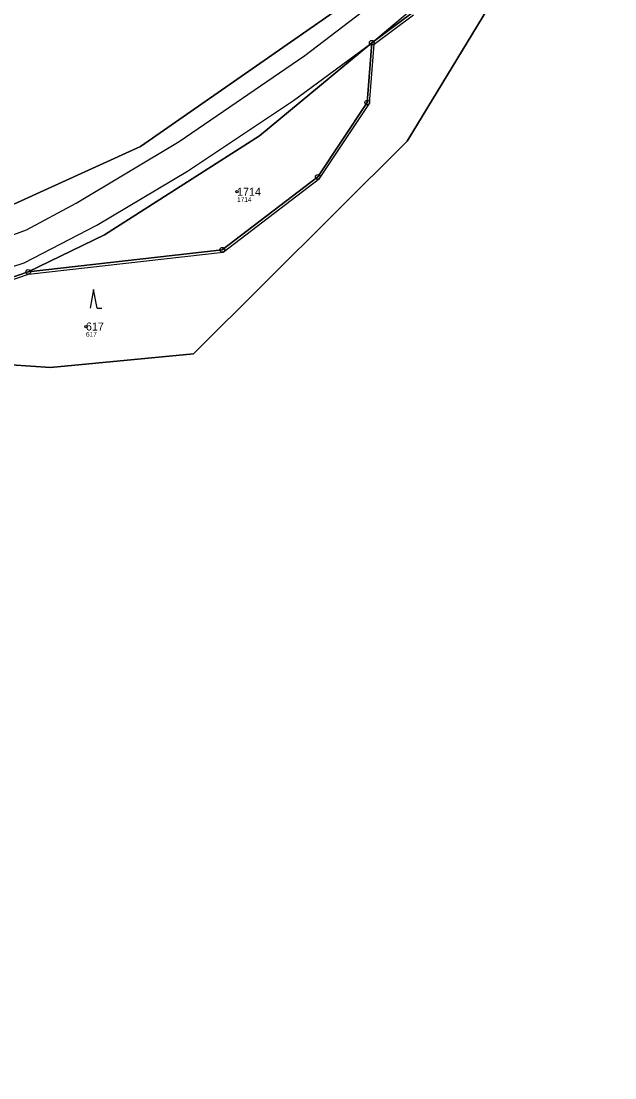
# Model space of a CAD drawing. Extents: x -770088 to -765625, y -1057899 to -1053934.
# Drawn here: x -768186.2 to -768060.2, y -1055836.3 to -1055611.9 of the extents above; entities that cross this region are included whole.
import ezdxf

# ---------------------------------------------------------------- set-up
doc = ezdxf.new("R2010")
doc.units = 0
for name, color, linetype in [('Definiční body', 7, 'Continuous'), ('Hranice parcel', 7, 'Continuous'), ('Parcelní čísla', 7, 'Continuous'), ('Polygon parcely', 7, 'Continuous'), ('Vnitřní kresba', 7, 'Continuous'), ('Značky bodu BP', 7, 'Continuous'), ('Značky kultur', 7, 'Continuous')]:
    doc.layers.add(name, color=color, linetype=linetype)

msp = doc.modelspace()

# ---------------------------------------------------------------- linework, layer by layer
at = {"layer": 'Definiční body'}
for centre in [(-768140.38, -1055648.13), (-768172.45, -1055676.74)]:
    msp.add_circle(centre, 0.25, dxfattribs=at)
at = {"layer": 'Hranice parcel'}
msp.add_line((-768111.79, -1055616.51), (-768103.19, -1055610.16), dxfattribs=at)
for points in [[(-768196.77, -1055684.34), (-768179.99, -1055685.43), (-768149.61, -1055682.54), (-768104.29, -1055637.41), (-768086.16, -1055607.62), (-767983.52, -1055552.84)], [(-768112.56, -1055604.82), (-768160.87, -1055638.55), (-768198.11, -1055655.41), (-768243.55, -1055665.87), (-768292.03, -1055669.76)], [(-768184.7, -1055665.16), (-768143.51, -1055660.46), (-768123.27, -1055644.97), (-768112.75, -1055629.19), (-768111.79, -1055616.51)], [(-768111.79, -1055616.51), (-768135.64, -1055636.25), (-768168.5, -1055657.24), (-768184.7, -1055665.16)], [(-768302.12, -1055683.68), (-768296.49, -1055681.79), (-768292.08, -1055680.32), (-768283.96, -1055679.54), (-768259.94, -1055677.57), (-768237.46, -1055675.58), (-768220.27, -1055672.71), (-768216.46, -1055672.25), (-768209.02, -1055673.46), (-768184.7, -1055665.16)]]:
    msp.add_lwpolyline(points, dxfattribs=at)
at = {"layer": 'Polygon parcely'}
for points in [[(-768112.56, -1055604.82), (-768160.87, -1055638.55), (-768198.11, -1055655.41), (-768243.55, -1055665.87), (-768292.03, -1055669.76), (-768317.01, -1055680.13), (-768323.05, -1055682.64), (-768370.97, -1055702.51), (-768420.02, -1055724.02), (-768455.1, -1055741.72)], [(-768198.11, -1055655.41), (-768160.87, -1055638.55), (-768112.56, -1055604.82)], [(-768086.16, -1055607.62), (-768104.29, -1055637.41), (-768149.61, -1055682.54), (-768179.99, -1055685.43), (-768196.77, -1055684.34), (-768194.75, -1055692.38), (-768224.62, -1055720.54), (-768278.26, -1055739.56), (-768269.37, -1055772.05), (-768226.85, -1055813.83), (-768208.15, -1055859.21), (-768196.97, -1055880.9), (-768222.04, -1055883.64), (-768256.62, -1055887.41), (-768284.6, -1055911.68), (-768295.98, -1055921.55), (-768301.36, -1055926.65), (-768324.43, -1055938.67), (-768353.01, -1055951.04), (-768391.65, -1055965.9), (-768431.86, -1055976.92), (-768474.56, -1055997.15)], [(-768103.19, -1055610.16), (-768111.79, -1055616.51), (-768112.75, -1055629.19), (-768123.27, -1055644.97), (-768143.51, -1055660.46), (-768184.7, -1055665.16), (-768209.02, -1055673.46), (-768216.46, -1055672.25), (-768220.27, -1055672.71), (-768237.46, -1055675.58), (-768259.94, -1055677.57), (-768283.96, -1055679.54), (-768292.08, -1055680.32), (-768296.49, -1055681.79), (-768302.12, -1055683.68), (-768292.5, -1055699.58), (-768286.73, -1055711.22), (-768210.16, -1055683.15), (-768196.77, -1055684.34), (-768179.99, -1055685.43), (-768149.61, -1055682.54), (-768104.29, -1055637.41), (-768086.16, -1055607.62)], [(-768446.8, -1055753.76), (-768414.12, -1055736.49), (-768382.42, -1055722.23), (-768347.5, -1055706.52), (-768302.12, -1055683.68), (-768296.49, -1055681.79), (-768292.08, -1055680.32), (-768283.96, -1055679.54), (-768259.94, -1055677.57), (-768237.46, -1055675.58), (-768220.27, -1055672.71), (-768216.46, -1055672.25), (-768209.02, -1055673.46), (-768184.7, -1055665.16), (-768168.5, -1055657.24), (-768135.64, -1055636.25), (-768111.79, -1055616.51), (-768103.19, -1055610.16)]]:
    msp.add_lwpolyline(points, dxfattribs=at)
msp.add_lwpolyline([(-768135.64, -1055636.25), (-768168.5, -1055657.24), (-768184.7, -1055665.16), (-768143.51, -1055660.46), (-768123.27, -1055644.97), (-768112.75, -1055629.19), (-768111.79, -1055616.51)], close=True, dxfattribs=at)
at = {"layer": 'Vnitřní kresba'}
for p, q in [((-768126.03, -1055619.21), (-768106.98, -1055604.62)), ((-768111.79, -1055616.51), (-768103.81, -1055609.78)), ((-768111.31, -1055616.77), (-768102.92, -1055610.58)), ((-768128.44, -1055628.75), (-768111.79, -1055616.51)), ((-768112.26, -1055629.37), (-768111.31, -1055616.77)), ((-768152.69, -1055637.46), (-768126.03, -1055619.21)), ((-768150.9, -1055643.75), (-768128.44, -1055628.75)), ((-768122.9, -1055645.32), (-768112.26, -1055629.37)), ((-768174.56, -1055650.53), (-768152.69, -1055637.46)), ((-768170.16, -1055655.23), (-768150.9, -1055643.75)), ((-768143.32, -1055660.95), (-768122.9, -1055645.32)), ((-768185.09, -1055656.21), (-768174.56, -1055650.53)), ((-768202.09, -1055662.51), (-768185.09, -1055656.21)), ((-768185.54, -1055663.21), (-768170.16, -1055655.23)), ((-768184.61, -1055665.65), (-768143.32, -1055660.95)), ((-768205.54, -1055669.8), (-768185.54, -1055663.21)), ((-768208.97, -1055673.97), (-768184.61, -1055665.65))]:
    msp.add_line(p, q, dxfattribs=at)
at = {"layer": 'Značky bodu BP'}
for centre, radius in [((-768111.79, -1055616.51), 0.5), ((-768111.79, -1055616.51), 0.0303), ((-768112.75, -1055629.19), 0.5), ((-768112.75, -1055629.19), 0.0303), ((-768123.27, -1055644.97), 0.5), ((-768123.27, -1055644.97), 0.0303), ((-768143.51, -1055660.46), 0.5), ((-768143.51, -1055660.46), 0.0303), ((-768184.7, -1055665.16), 0.5), ((-768184.7, -1055665.16), 0.0303)]:
    msp.add_circle(centre, radius, dxfattribs=at)
at = {"layer": 'Značky kultur'}
for p, q in [((-768170.84, -1055668.85), (-768171.59, -1055672.85)), ((-768170.09, -1055672.85), (-768170.84, -1055668.85)), ((-768170.09, -1055672.85), (-768169.09, -1055672.85))]:
    msp.add_line(p, q, dxfattribs=at)

# ---------------------------------------------------------------- texts
at = {"layer": 'Definiční body'}
for s, p in [('1714', (-768140.38, -1055650.29)), ('617', (-768172.45, -1055678.9))]:
    msp.add_text(s, height=1, dxfattribs=at).set_placement(p)
at = {"layer": 'Parcelní čísla'}
for s, p in [('1714', (-768140.38, -1055648.98)), ('617', (-768172.45, -1055677.59))]:
    msp.add_text(s, height=1.7, dxfattribs=at).set_placement(p)

doc.saveas('drawing.dxf')
